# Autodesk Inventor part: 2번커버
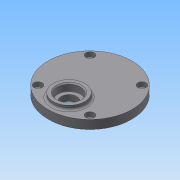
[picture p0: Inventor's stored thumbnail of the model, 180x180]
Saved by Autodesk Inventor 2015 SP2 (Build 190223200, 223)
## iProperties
Created: 2015-06
Part Number: 2번커버
Material: 일반
Document SubType Name: Modeling
Designer: AMC
Density: 1 g/cm^3
Appearance: 기본값
Author: AMC
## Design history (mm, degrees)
sketch "스케치1"
  geometry: C1 r 40 at (0, 0); 1 further point
  constraints: 1 centre point, 1 coincident
  dimensions: "d0" = 80 diameter of C1
extrude "돌출1" new body sketch "스케치1" distance "d1" = 9; taper "d2" = 0 deg
sketch "스케치2" dims "d3" = 70
  geometry: L1 (0, 0)-(0, 43.819); L2 (0, 0)-(32.382, 32.382); C1 r 40 at (0, 0) reference; 3 further points
  constraints: 4 end point, 1 coincident, 1 point on line, 1 vertical, 3 other
  dimensions: "d4" = 45 deg angle of L1 L2
hole "구멍1" sketch "스케치2" at (24.749, 24.749) diameter "d5" = 4.5; stored, may be unused: countersink angle "d9" = 90 deg, drill point angle "d11" = 118 deg; dims "d6" = 6, "d7" = 8, "d8" = 4.4, "d10" = 8
chamfer "모따기1" distance "d15" = 1; stored, may be unused: second distance "d16" = 2, angle "d17" = 45 deg
sketch "스케치3"
  geometry: C1 r 14 at (0, 11); C2 r 14 at (0, -20); 1 further point
  constraints: 2 centre point, 2 vertical alignment
  dimensions: "d18" = 28 diameter of C1; "d19" = 28 diameter of C2; "d20" = 20 distance of point (0, 0) C2.centre; "d21" = 11 distance of C1.centre point (0, 0)
extrude "돌출2" join sketch "스케치3" distance "d22" = 3; taper "d23" = 0 deg
sketch "스케치4"
  geometry: C1 r 14 at (0, -20) reference; C2 r 15 at (0, -20); 1 further point
  constraints: 1 centre point, 1 coincident
  dimensions: "d24" = 30 diameter of C2
extrude "돌출3" join sketch "스케치4" distance "d25" = 4; taper "d26" = 0 deg
sketch "스케치5"
  geometry: L1 (-39, 0)-(-40, 1) reference; L2 (-40, 1)-(-40, 9) reference; L3 (-40, 9)-(-35, 9) reference; L4 (-35, 9)-(-35, 13) reference; L5 (-35, 13)-(-5, 13) reference; L6 (-5, 13)-(-5, 9) reference; L7 (-5, 9)-(40, 9) reference; L8 (40, 9)-(40, 1) reference; L9 (40, 1)-(39, 0) reference; L10 (39, 0)-(25, 0) reference; L11 (25, 0)-(25, -3) reference; L12 (25, -3)-(-3, -3) reference; L13 (-3, -3)-(-3, 0) reference; L14 (-3, 0)-(-6, 0) reference; L15 (-6, 0)-(-6, -3) reference; L16 (-6, -3)-(-34, -3) reference; L17 (-34, -3)-(-34, 0) reference; L18 (-34, 0)-(-39, 0) reference; L19 (-3, -3)-(25, -3) reference; L20 (-34, -3)-(-6, -3) reference; L21 (-9, 13)-(-9, 6.3); L22 (-9.3, 6)-(-12.5, 6); L23 (-12.5, 6)-(-12.5, 4); L24 (-12.5, 4)-(-9.3, 4); L25 (-9, 3.7)-(-9, -3); L26 (-20, -3)-(-20, 21); L27 (-9, 13)-(-20, 13); L28 (-5, 13)-(-35, 13) reference; L29 (-9, -3)-(-20, -3); L30 (-20, 13)-(-20, -3); A1 r 0.3 centre (-9.3, 6.3) between (-9.3, 6) and (-9, 6.3); A2 r 0.3 centre (-9.3, 3.7) between (-9, 3.7) and (-9.3, 4); 2 further points
  constraints: 18 end point, 4 perpendicular, 4 point on circle, 4 point on line, 4 tangent, 2 centre point, 2 collinear, 2 midpoint, 2 vertical, 1 equal radius
  dimensions: "d29" = 22 diameter of L21 L26; "d30" = 15 diameter of L23 L26; "d31" = 22 diameter of L25 L26; "d32" = 2 distance of L22.end L23.end; "d33" = 7 distance of point (-9, 4) L25.end; "d34" = 0.3 radius of A1
revolve "회전1" sketch "스케치5" stored, may be unused: angle "d35" = 90 deg
sketch "스케치6"
  geometry: L1 (40, 1)-(39, 0) reference; L2 (39, 0)-(25, 0) reference; L3 (25, 0)-(25, -3) reference; L4 (25, -3)-(-3, -3) reference; L5 (-3, -3)-(-3, 0) reference; L6 (-3, 0)-(-6, 0) reference; L7 (-6, 0)-(-6, -3) reference; L8 (-6, -3)-(-9, -3) reference; L9 (-9, -3)-(-9, 3.7) reference; L10 (-9.3, 4)-(-12.5, 4) reference; L11 (-12.5, 4)-(-12.5, 6) reference; L12 (-12.5, 6)-(-9.3, 6) reference; L13 (-9, 6.3)-(-9, 13) reference; L14 (-9, 13)-(-5, 13) reference; L15 (-5, 13)-(-5, 9) reference; L16 (-5, 9)-(40, 9) reference; L17 (40, 9)-(40, 1) reference; L18 (-39, 0)-(-40, 1) reference; L19 (-40, 1)-(-40, 9) reference; L20 (-40, 9)-(-35, 9) reference; L21 (-35, 9)-(-35, 13) reference; L22 (-35, 13)-(-31, 13) reference; L23 (-31, 13)-(-31, 6.3) reference; L24 (-30.7, 6)-(-27.5, 6) reference; L25 (-27.5, 6)-(-27.5, 4) reference; L26 (-27.5, 4)-(-30.7, 4) reference; L27 (-31, 3.7)-(-31, -3) reference; L28 (-31, -3)-(-34, -3) reference; L29 (-34, -3)-(-34, 0) reference; L30 (-34, 0)-(-39, 0) reference; L31 (-3, -3)-(25, -3) reference; L32 (11, -3)-(11, 21.435); L33 (22, -3)-(22, 3.7); L34 (21.7, 4)-(20, 4); L35 (20, 4)-(20, 5); L36 (20, 5)-(11, 5); L37 (22, -3)-(11, -3); L38 (11, -3)-(11, 5); A1 r 0.3 centre (-9.3, 3.7) between (-9, 3.7) and (-9.3, 4) reference; A2 r 0.3 centre (-9.3, 6.3) between (-9.3, 6) and (-9, 6.3) reference; A3 r 0.3 centre (-30.7, 6.3) between (-31, 6.3) and (-30.7, 6) reference; A4 r 0.3 centre (-30.7, 3.7) between (-30.7, 4) and (-31, 3.7) reference; A5 r 0.3 centre (21.7, 3.7) between (22, 3.7) and (21.7, 4); 2 further points
  constraints: 14 end point, 4 perpendicular, 4 point on line, 2 collinear, 2 point on circle, 2 tangent, 1 centre point, 1 midpoint, 1 vertical
  dimensions: "d36" = 22 diameter of L33 L32; "d37" = 18 diameter of L35 L32; "d38" = 7 distance of L33.start point (22, 4); "d39" = 1 distance of L34.end L35.end; "d40" = 0.3 radius of A5
revolve "회전2" sketch "스케치6" stored, may be unused: angle "d41" = 90 deg
fillet "모깎기1" dims "d42" = 2
fillet "모깎기2" dims "d43" = 2
fillet "모깎기3" dims "d44" = 2
chamfer "모따기2" distance "d45" = 1; stored, may be unused: second distance "d46" = 2, angle "d47" = 45 deg
node "솔리드1"
pattern_circular "원형 패턴1" dims angle "d13" = 360 deg
node "절단 모서리 투영1"
node "절단 모서리 투영2"
node "절단 모서리 투영3"
